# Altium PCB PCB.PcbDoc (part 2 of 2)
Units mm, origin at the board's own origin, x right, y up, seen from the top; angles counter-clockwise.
Board outline 68.58 x 53.34 mm, 4 copper layers (TOP, GND, SIG, BOTTOM), stack 1.586 mm thick; 137 components, 78 nets, 396 pads, 160 vias.
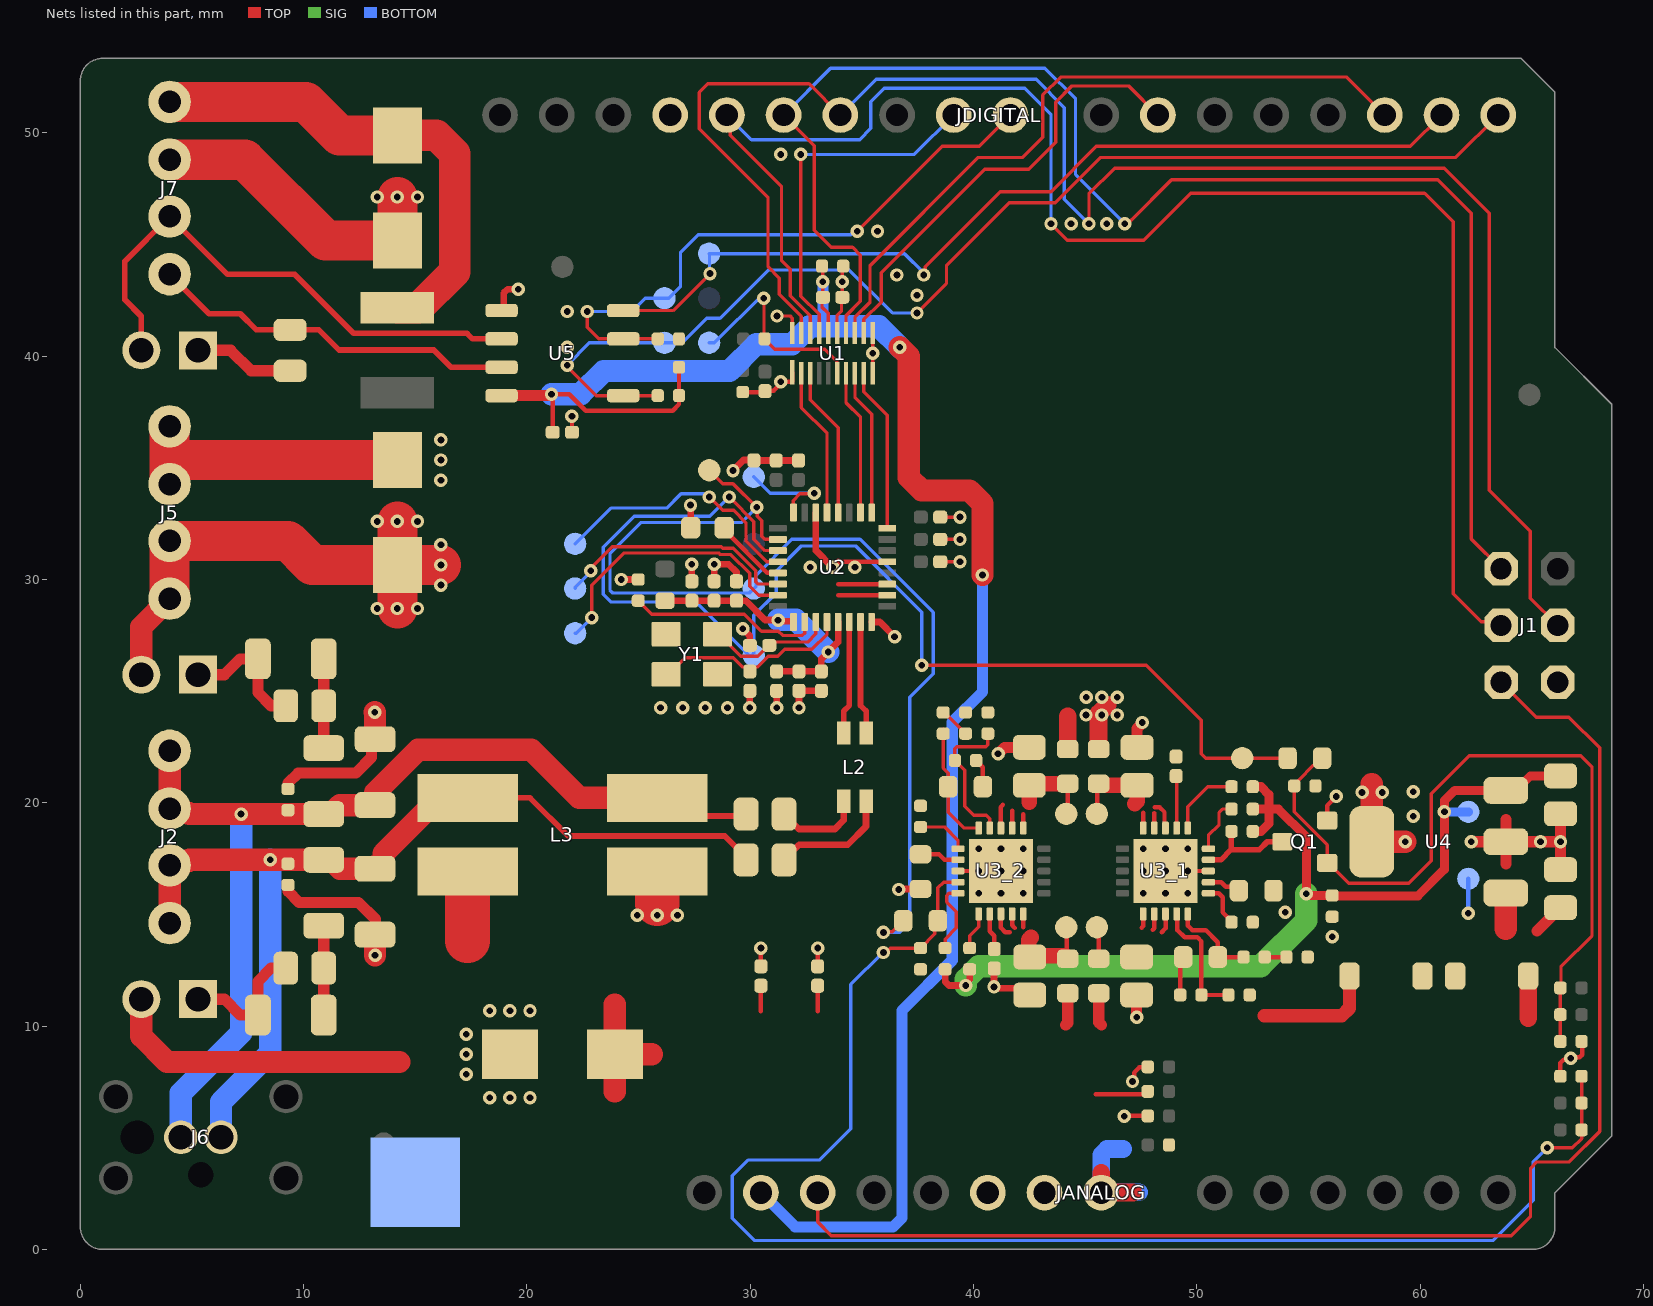
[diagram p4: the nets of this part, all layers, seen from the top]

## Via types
v1: diameter 0.6, hole 0.3, TOP to BOTTOM, tented both sides, 160 vias

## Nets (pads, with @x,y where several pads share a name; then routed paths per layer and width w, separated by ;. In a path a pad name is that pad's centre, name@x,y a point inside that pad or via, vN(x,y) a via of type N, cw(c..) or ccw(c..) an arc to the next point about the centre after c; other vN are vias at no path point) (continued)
DIGITAL8_1: DE.X JDIGITAL.9 R35.2 U5.3 | length 27.6
  TOP w0.15: v1(22.7,42) 22.7,41.3 23.225,40.775 U5.3@24.315,40.775 R35.2@25.861,40.775 ; v1(34.8,45.6) 38.6,49.4 40.256,49.4 JDIGITAL.9@41.656,50.8
  BOTTOM w0.15: v1(22.7,42) 24.706,42 25.301,42.595 26.36,42.595 26.877,43.111 26.877,44.642 27.67,45.435 34.513,45.435 34.678,45.6 v1(34.8,45.6)
DIOA0_1: DIOA0.X DIOA0_1.X R14.1 U2.18 | length 48
  TOP w0.15: DIOA0_1.X@28.165,34.895 28.765,34.295 29.23,34.295 v1(30.294,33.231) 30.317,33.208 30.317,32.831 30.517,32.631 30.517,31.938 30.66,31.795 U2.18@31.24,31.795 ; v1(35.965,14.195) 35.998,14.228 36.365,14.228 36.527,14.39 36.529,14.39 36.854,14.715 R14.1@36.854,14.717
  BOTTOM w0.15: v1(30.294,33.231) 29.618,32.555 25.12,32.555 23.718,31.153 23.718,29.529 23.852,29.395 29.96,29.395 DIOA0.X@30.16,29.595 30.26,29.695 30.26,30.195 31.865,31.8 34.919,31.8 38.196,28.524 38.196,25.774 37.141,24.719 37.141,19.133 37.151,19.122 37.151,14.651 36.695,14.195 v1(35.965,14.195)
DIOA1_1: DIOA1.X DIOA1_1.X R16.2 U2.19 | length 53.9
  TOP w0.15: v1(29.06,33.695) 29.635,33.12 29.635,33.11 30.163,32.582 30.163,31.792 30.66,31.295 U2.19@31.24,31.295 ; v1(37.684,26.16) 47.74,26.16 50.2,23.7 50.2,22.2 50.4,22 DIOA1_1.X@52.033,22 R16.2@54.067,22
  BOTTOM w0.15: v1(29.06,33.695) 28.197,32.832 24.797,32.832 23.419,31.454 23.419,29.334 23.759,28.995 27.56,28.995 29.96,26.595 30.06,26.595 30.16,26.695 30.16,27.585 30.162,27.587 30.162,28.397 31.16,29.395 31.16,30.368 32.292,31.5 34.722,31.5 37.684,28.538 v1(37.684,26.16)
GND: C1_1.2 C1_2.2 C2.1 C3.2 C4.1 C5.1 C6.1 C7.1 C8.1 C9.1 C10.1 C11.1 C12.1 C13.1 C14.1 C19.2 C20_1.1 C20_2.1 C21.1 C22.1 C23.1 C24_1.2 C24_2.2 C25.1 C26.1 C27.1 C28.1 C29.1 D3.2 D4.1 D5.2 F1.1 F3.1 J1.6 J3.2 J4.2 J5.1 J5.2 J7.3 JANALOG.6 JANALOG.7 JDIGITAL.15 L3.2 Q1.2 QR1.PAD R3.2 R4.2 R5.2 R9.2 R21.2 R22.2 R23.2 R24.1 R25.1 R26.2 R30.1 R31.1 R35.1 R36_1.1 R36_2.1 R38_1.1 R38_2.1 R39_1.1 R39_2.1 R40_1.1 R40_2.1 U1.1 U1.10 U1.11 U1.15 U1.20 U2.2 U2.3 U2.5 U2.14 U2.32 U2.33 U3_1.8 U3_1.21 U3_2.8 U3_2.21 U4.2 U4.4 U5.5 Y1.2 Y1.4 | length 131
  TOP w0.15: v1(31.2,41.8) 31.8,41.8 31.89,41.71 U1.20@31.89,41.038 ; U1.15@33.89,41.038 33.89,41.838 34.09,42.038 34.09,42.603 C4.1@34.125,42.638 v1(34.125,43.337) 34.125,43.998 R21.2@34.165,44.038 ; U1.10@35.49,39.238 v1(35.49,40.138) U1.11@35.49,41.038 ; C10.1@38.51,30.795 v1(39.395,30.795) ; C27.1@38.51,31.795 v1(39.395,31.795) ; C13.1@38.51,32.795 v1(39.395,32.795)
  TOP w0.2: v1(22.015,37.306) 22.02,37.301 22.02,36.6 C28.1@22.025,36.595 ; R22.2@29.665,38.395 30.625,38.395 30.69,38.46 31.055,38.46 31.373,38.778 v1(31.373,38.854) 31.89,38.854 U1.1@31.89,39.288 ; C29.1@30.48,12.685 v1(30.48,13.493) ; C25.1@33.02,12.685 v1(33.02,13.493) ; 33.94,29.295 U2.2@36.14,29.295 ; 33.94,29.795 U2.3@36.14,29.795 ; 33.94,30.795 U2.5@36.14,30.795 ; U3_2.8@39.304,16.945 v1(40.229,16.945) ; v1@46.763,5.975 R24.1@47.805,5.975 ; v1(47.121,7.517) 47.195,7.592 47.195,7.917 47.43,8.152 47.782,8.152 R25.1@47.805,8.175 ; v1@47.282,10.311 v1@47.305,10.334 ; v1(49.596,16.945) U3_1.8@50.521,16.945 ; Q1.2@55.84,19.206 55.84,19.875 v1(56.251,20.286) ; R30.1@66.282,7.754 66.282,8.347 66.423,8.489 66.67,8.489 v1(66.747,8.565) 66.784,8.603 67.139,8.603 67.257,8.72 67.257,9.288 R31.1@67.232,9.313
  TOP w0.3: U5.5@18.96,42.114 18.96,42.824 19.136,43 v1(19.611,43) ; v1(24.22,30) R3.2@24.985,30 ; v1(27.328,33.334) 27.332,33.33 27.332,32.323 C14.1@27.335,32.32 ; C21.1@27.385,29.92 v1(27.385,30.685) ; C7.1@28.385,29.92 v1(28.385,30.685) 29.035,30.685 29.385,30.335 C22.1@29.385,29.92 ; v1(29.231,34.878) 29.703,35.35 30.025,35.35 30.045,35.33 C11.1@31.165,35.33 C12.1@32.165,35.33 ; v1(29.66,27.795) 29.985,27.47 C5.1@29.985,27.05 ; v1(29.985,24.25) C9.1@29.985,25.015 ; v1(31.185,24.25) C6.1@31.185,25.015 ; v1(32.185,24.25) C8.1@32.185,25.015 C23.1@33.185,25.015 ; U2.14@32.94,32.995 32.94,31.295 v1(33.69,30.545) 33.94,30.795 ; U2.32@35.44,28.095 35.807,28.095 v1(36.465,27.437) ; v1(36.649,16.117) 36.674,16.142 R38_2.1@37.629,16.142 ; C20_2.1@40.919,12.572 v1(40.919,11.754) 40.977,11.697 42.216,11.697 C1_2.2@42.52,11.392
  TOP w0.5: F1.1@9.3,16.32 9.3,16.04 9.8,15.54 12.459,15.54 13.214,14.784 R4.2@13.214,14.109 ; F3.1@9.3,20.62 9.3,20.877 9.762,21.339 12.339,21.339 13.04,22.04 13.04,22.685 R5.2@13.2,22.845 ; v1(41.101,22.195) 41.387,22.481 C24_2.2@42.499,22.482 ; v1(47.305,10.392) C24_1.2@47.305,11.392 ; C1_1.2@47.326,22.482 47.326,23.334 47.56,23.568 v1(47.56,23.595) ; v1(62.29,18.256) U4.2@63.84,18.256 ; 63.84,17.256 U4.2@63.84,18.256 ; 63.84,19.256 U4.2@63.84,18.256 ; C3.2@66.29,17.006 v1(66.29,18.256) ; C19.2@66.29,19.506 v1(66.29,18.256) ; U4.2@63.84,18.256 v1(65.39,18.256) v1(66.29,18.256)
  TOP w1: J3.2@2.73,11.205 2.73,9.551 3.888,8.392 14.284,8.392 ; J4.2@2.73,25.735 2.73,27.87 J5.1@4,29.14 ; v1(13.185,24.05) 13.2,24.035 R5.2@13.2,22.845 ; v1(13.2,13.17) R4.2@13.2,14.095 ; 57.84,20.84 U4.4@57.84,18.256 v1(59.34,18.256)
  TOP w1.8: J5.1@4,29.14 J5.2@4,31.73 9.305,31.73 10.385,30.65 D5.2@14.2,30.65 ; J7.3@4,48.8 7.365,48.8 10.985,45.18 D4.1@14.2,45.18 v1(14.2,47.13) ; v1(14.2,28.7) D5.2@14.2,30.65 ; v1(14.2,32.6) D5.2@14.2,30.65 ; v1(16.15,30.65) D5.2@14.2,30.65
  TOP w2: 25.84,15.487 L3.2@25.84,16.92
  other v1: 46.749,5.961 18.34,6.787 19.24,6.787 20.14,6.787 17.29,7.837 17.29,8.737 17.29,9.637 18.34,10.687 19.24,10.687 20.14,10.687 56.06,14.003 24.94,14.97 25.84,14.97 26.74,14.97 53.96,15.095 40.229,15.945 41.229,15.945 42.229,15.945 47.596,15.945 48.596,15.945 49.596,15.945 41.229,16.945 42.229,16.945 47.596,16.945 48.596,16.945 40.229,17.945 41.229,17.945 42.229,17.945 47.596,17.945 48.596,17.945 49.596,17.945 59.7,19.4 57.402,20.464 58.302,20.464 59.7,20.5 25.985,24.25 26.985,24.25 27.985,24.25 28.985,24.25 13.3,28.7 15.1,28.7 16.15,29.75 32.69,30.545 34.69,30.545 16.15,31.55 13.3,32.6 15.1,32.6 21.8,40.4 21.8,42 37.47,42.735 36.57,43.635 35.7,45.6 44.37,45.935 45.97,45.935 13.3,47.13 15.1,47.13 31.37,49.035
I\R\Q\_\N\_2: U1.8 U2.9 | length 6.6
  TOP w0.15: U1.8@34.69,39.238 34.69,38.156 35.44,37.406 U2.9@35.44,32.995
IOREF: C4.2 C28.2 JANALOG.2 R21.1 R32.2 R33.2 U1.16 U5.8 | length 84.7
  TOP w0.15: R21.1@33.215,44.038 33.255,43.998 v1(33.255,43.337) C4.2@33.255,42.638 33.215,42.598 33.215,42.194 33.49,41.919 U1.16@33.49,41.038
  TOP w0.2: C28.2@21.155,36.595 21.155,38.245 v1(21.1,38.3) 21.9,38.3 22.641,37.559 26.525,37.559 26.811,37.845 R32.2@26.811,38.235 R33.2@26.811,39.505
  TOP w0.5: U5.8@18.865,38.235 21.008,38.235 21.073,38.3 v1(21.1,38.3)
  TOP w1: v1(36.7,40.4) 37.1,40 37.1,34.568 37.686,33.982 39.814,33.982 40.4,33.397 v1(40.4,30.2)
  BOTTOM w0.5: JANALOG.2@30.48,2.54 32.02,1 36.4,1 36.8,1.4 36.8,10.7 39.048,12.948 39.048,23.618 40.4,24.97 v1(40.4,30.2) ; v1(33.255,43.337) 33.255,41.65 33.57,41.335
  BOTTOM w1: v1(21.1,38.3) 22.409,38.3 23.444,39.335 29.07,39.335 30.27,40.535 31.87,40.535 32.67,41.335 33.57,41.335 35.765,41.335 v1(36.7,40.4)
LDO_OUT: C19.1 LDO_OUT.X R8.1 R10_1.2 R10_2.2 R11_1.2 R11_2.2 R26.1 U4.3 | length 45.2
  TOP w0.3: R10_2.2@38.729,12.542 38.729,11.993 38.905,11.817 v1(39.654,11.817) 39.654,11.898 39.829,12.073 R11_2.2@39.829,12.542
  TOP w0.4: R8.1@52.508,18.72 52.879,18.72 53.229,19.071 53.229,19.72 ; R10_1.2@52.508,19.72 53.229,19.72 ; R11_1.2@52.508,20.72 52.879,20.72 53.229,20.37 53.229,19.72 ; C19.1@66.29,21.206 64.944,21.206 64.294,20.556 61.552,20.556 61.089,20.093 61.089,17.015 59.905,15.832 56.081,15.832 R26.1@56.064,15.849 54.988,15.849 v1(54.905,15.932) 54.905,18.469 53.654,19.72 53.229,19.72
  SIG w1: v1(39.654,11.817) 39.654,12.095 40.24,12.681 52.857,12.681 54.905,14.729 v1(54.905,15.932)
  BOTTOM w0.4: v1(61.09,19.595) LDO_OUT.X@62.16,19.595
MISO_1: J1.1 JDIGITAL.13 U1.14 | length 66.5
  TOP w0.15: JDIGITAL.13@31.496,50.8 32.865,49.431 32.865,45.643 33.635,44.873 34.582,44.873 34.925,44.53 34.925,42.454 34.29,41.82 U1.14@34.29,41.038 ; v1(46.77,45.935) 46.892,45.935 47.047,46.09 47.057,46.09 48.867,47.9 60.8,47.9 62.294,46.406 62.294,31.813 J1.1@63.627,30.48
  BOTTOM w0.15: JDIGITAL.13@31.496,50.8 33.596,52.9 43.2,52.9 44.57,51.53 44.57,48.135 v1(46.77,45.935)
MOSI_1: J1.4 JDIGITAL.12 U1.19 | length 76.9
  TOP w0.15: U1.19@32.29,41.038 32.29,41.781 31.3,42.771 31.3,43.5 30.8,44 30.8,47.088 27.712,50.176 27.712,51.812 28.1,52.2 32.636,52.2 JDIGITAL.12@34.036,50.8 ; v1(45.17,45.935) 45.17,47.27 46.318,48.418 61.082,48.418 63.1,46.4 63.1,34 64.94,32.16 64.94,29.167 J1.4@66.167,27.94
  BOTTOM w0.15: JDIGITAL.12@34.036,50.8 35.636,52.4 42.805,52.4 44.07,51.135 44.07,47.035 v1(45.17,45.935)
NetC1_1_1: C1_1.1 OUT_1.X R2_1.2 U3_1.13 U3_1.14 U3_1.15 | length 6.5
  TOP w0.2: OUT_1.X@45.546,19.526 R2_1.2@45.546,20.857 ; U3_1.15@47.596,18.87 47.596,19.554 ; U3_1.14@48.096,18.87 48.096,19.542 ; 48.126,19.805 48.332,19.805 48.553,19.584 U3_1.13@48.553,18.87
  TOP w0.7: R2_1.2@45.605,20.857 45.665,20.797 45.943,20.797 R2_1.2@45.962,20.778 ; R2_1.2@45.968,20.778 C1_1.1@47.322,20.778 ; 47.226,19.963 47.326,20.063 C1_1.1@47.326,20.782
NetC1_2_1: C1_2.1 OUT_2.X R2_2.2 U3_2.13 U3_2.14 U3_2.15 | length 6.3
  TOP w0.2: U3_2.13@41.229,15.02 41.229,14.402 41.426,14.205 41.626,14.205 ; U3_2.14@41.729,15.02 41.729,14.517 41.852,14.393 ; 42.229,14.426 U3_2.15@42.229,15.02 ; R2_2.2@44.176,13.074 OUT_2.X@44.176,14.389
  TOP w0.7: 42.577,13.968 42.477,13.868 42.477,13.149 44.101,13.149 R2_2.2@44.176,13.074
NetC3_1: "POWER OR.X" C3.1 D1.C D2.C U4.1 | length 4.6
  TOP w0.5: 65.24,14.256 C3.1@66.29,15.306
  TOP w1: 63.84,14.356 U4.1@63.84,15.956
  BOTTOM w0.2: v1(62.16,15.056) 62.16,16.595
NetC5_2: C5.2 U2.27 Y1.3 | length 5.8
  TOP w0.15: Y1.3@28.535,27.55 28.58,27.55 29.351,26.779 29.572,26.558 30.338,26.558 30.83,27.05 30.878,27.05 31.027,27.199 32.575,27.199 32.94,27.565 U2.27@32.94,28.095
NetC6_2: C6.2 C7.2 C8.2 C21.2 C22.2 C23.2 L1.2 U2.25 U2.29 | length 13.5
  TOP w0.3: L1.2@26.185,29.05 C21.2@27.385,29.05 C7.2@28.385,29.05 29.808,29.05 30.671,28.187 31.24,28.187 v1(31.247,28.18) 31.304,28.124 31.94,28.124 U2.25@31.94,28.095 ; C6.2@31.185,25.885 C23.2@33.185,25.885 33.185,26.447 v1(33.492,26.754) 33.94,27.202 U2.29@33.94,28.095
  BOTTOM w1: v1@31.26,28.195 32.052,28.195 v1(33.492,26.754)
NetC9_2: C9.2 U2.28 Y1.1 | length 9
  TOP w0.15: Y1.1@26.235,25.75 26.335,25.75 27.087,26.502 29.237,26.502 29.66,26.078 29.792,26.078 C9.2@29.985,25.885 30.178,26.078 30.315,26.078 30.518,26.281 30.52,26.281 30.797,26.558 31.231,26.558 31.542,26.869 32.755,26.869 33.44,27.554 U2.28@33.44,28.095
NetC14_2: C14.2 U2.21 | length 3.1
  TOP w0.2: C14.2@28.943,32.12 30.768,30.295 U2.21@31.24,30.295
NetC15_1: C15.1 L2.2 | length 4
  TOP w0.3: C15.1@31.515,19.495 31.515,19.369 31.912,18.971 32.038,18.971 32.181,18.829 33.797,18.829 34.19,19.222 L2.2@34.19,20.075
NetC15_2: C15.2 F3.2 J2.3 J2.4 J6.1 L3.1 R5.1 R7.1 | length 46.8
  TOP w0.254: L3.1@25.84,20.22 26.653,19.407 29.727,19.407 C15.2@29.815,19.495
  TOP w1: J2.4@4,22.33 J2.3@4,19.74 4.172,19.568 4.809,19.568 4.881,19.495 11.23,19.495 11.63,19.895 R5.1@13.1,19.895 ; R5.1@13.2,19.895 13.2,20.444 15.126,22.37 20.196,22.37 22.346,20.22 L3.1@25.84,20.22
  BOTTOM w1: J6.1@4.5,5.02 4.5,7 7.2,9.7 v1@7.2,19.5
  other v1: 7.2,19.495
NetC16_1: C16.1 L2.3 | length 5.5
  TOP w0.3: C16.1@31.515,17.445 31.515,17.571 31.912,17.968 32.038,17.968 32.192,18.122 34.368,18.122 35.19,18.944 L2.3@35.19,20.075
NetC16_2: C16.2 F1.2 J2.1 J2.2 J6.2 L3.4 R4.1 R6.1 | length 44.6
  TOP w0.254: L3.4@17.34,20.22 20.14,20.22 21.85,18.51 28.863,18.51 29.815,17.558 C16.2@29.815,17.445
  TOP w1: J2.1@4,14.61 J2.2@4,17.2 4.172,17.372 4.809,17.372 4.881,17.445 R6.1@10.9,17.445 ; R6.1@11.23,17.445 11.63,17.045 R4.1@13.1,17.045 ; R4.1@13.2,17.155 R4.1@13.2,17.045 13.497,17.045 13.577,17.125 13.577,17.725 15.497,19.645 16.765,19.645 L3.4@17.34,20.22
  BOTTOM w1: J6.2@6.3,5.02 6.3,6.6 8.5,8.8 v1(8.5,17.445)
NetC17_1: C17.1 R6.2 R27.1 | length 4
  TOP w0.5: R27.1@10.9,10.495 C17.1@10.9,12.595 R6.2@10.9,14.495
NetC17_2: C17.2 J3.1 R27.2 | length 5.6
  TOP w0.5: J3.1@5.27,11.205 6.451,11.205 7.161,10.495 R27.2@7.95,10.495 ; R27.2@7.95,10.825 7.95,12 8.545,12.595 C17.2@9.2,12.595
NetC18_1: C18.1 R7.2 R41.1 | length 4
  TOP w0.5: R7.2@10.9,22.445 C18.1@10.9,24.345 R41.1@10.9,26.445
NetC18_2: C18.2 J4.1 R41.2 | length 5.6
  TOP w0.5: J4.1@5.27,25.735 6.451,25.735 7.161,26.445 R41.2@7.95,26.445 ; R41.2@7.95,26.115 7.95,24.94 8.545,24.345 C18.2@9.2,24.345
NetC20_1_2: C20_1.2 U3_1.12 | length 2.3
  TOP w0.15: C20_1.2@49.077,21.197 49.096,21.177 U3_1.12@49.096,18.87
NetC20_2_2: C20_2.2 U3_2.12 | length 1.7
  TOP w0.2: U3_2.12@40.729,15.02 40.729,14.249 40.929,14.049 C20_2.2@40.929,13.452
NetC24_1_1: C24_1.1 IN_1.X R12_1.2 R13_1.2 R15_1.1 U3_1.1 U3_1.2 U3_1.3 | length 5.3
  TOP w0.2: R15_1.1@45.599,13.024 IN_1.X@45.599,14.271 ; 47.526,14.405 47.602,14.482 U3_1.1@47.602,15.015 ; 48.026,14.305 48.102,14.382 U3_1.2@48.102,15.015 ; 48.426,14.205 48.602,14.382 U3_1.3@48.602,15.015 ; R12_1.2@49.258,11.392 49.258,12.957 R13_1.2@49.393,13.092
  TOP w0.7: R15_1.1@45.605,13.017 R15_1.1@45.617,13.005
NetC24_2_1: C24_2.1 IN_2.X R12_2.2 R13_2.2 R15_2.1 U3_2.1 U3_2.2 U3_2.3 | length 7.8
  TOP w0.2: R12_2.2@40.117,21.897 40.117,21.889 40.417,21.59 R13_2.2@40.417,20.782 ; 41.223,19.809 41.32,19.905 ; U3_2.3@41.229,18.87 41.229,19.645 41.229,19.809 ; U3_2.2@41.729,18.87 41.729,19.645 ; U3_2.1@42.229,18.87 42.229,19.494 ; IN_2.X@44.22,19.541 R15_2.1@44.22,20.857
  TOP w0.7: 42.499,20.022 C24_2.1@42.499,20.782 ; C24_2.1@42.72,20.576 42.514,20.782 42.589,20.857 R15_2.1@44.214,20.857
NetD4_2: D4.2 F2.2 J7.4 | length 22.3
  TOP w1.4: F2.2@14.2,42.165 15.15,42.165 16.77,43.785 16.77,49.08 15.95,49.9 14.22,49.9 D4.2@14.2,49.88
  TOP w1.8: J7.4@4,51.39 10.1,51.39 11.61,49.88 D4.2@14.2,49.88
NetDIO_B0_X: DIO_B0.X U2.16 | length 4.6
  TOP w0.15: U2.16@31.94,32.995 31.92,33.015 31.92,33.532 32.225,33.837 32.844,33.837 v1(32.868,33.861)
  BOTTOM w0.15: DIO_B0.X@30.16,34.595 30.894,33.861 v1(32.868,33.861)
NetDIOA2_X: DIOA2.X U2.20 | length 11.7
  TOP w0.15: v1(28.16,33.695) 28.76,33.095 29.258,33.095 29.809,32.544 29.809,31.725 30.74,30.795 U2.20@31.24,30.795
  BOTTOM w0.15: DIOA2.X@22.16,31.595 23.765,33.2 26.265,33.2 26.901,33.836 27.898,33.836 28.038,33.695 v1(28.16,33.695)
NetDIOA3_X: DIOA3.X U2.22 | length 10.9
  TOP w0.15: v1(22.86,30.395) 22.86,30.495 23.829,31.464 28.708,31.464 28.776,31.395 29.241,31.395 30.249,30.387 30.249,29.905 30.36,29.795 U2.22@31.24,29.795
  BOTTOM w0.15: DIOA3.X@22.16,29.595 22.16,29.645 22.86,30.345 v1(22.86,30.395)
NetDIOA4_X: DIOA4.X U2.23 | length 12.5
  TOP w0.15: v1(22.91,28.295) 22.91,29.735 24.362,31.187 28.593,31.187 28.662,31.118 29.126,31.118 29.972,30.272 29.972,29.698 30.376,29.295 U2.23@31.24,29.295
  BOTTOM w0.15: DIOA4.X@22.16,27.595 22.21,27.595 v1(22.91,28.295)
NetJ7_1: J7.1 R34.2 U5.7 | length 16.6
  TOP w0.254: J7.1@4,43.67 5.77,41.9 7.165,41.9 7.885,41.18 R34.2@9.395,41.18 10.685,41.18 11.591,40.274 15.831,40.274 16.6,39.505 U5.7@18.865,39.505
NetJ7_2: J7.2 J12.2 U5.6 | length 24.3
  TOP w0.254: J12.2@2.73,40.265 2.73,41.79 1.995,42.525 1.995,44.255 J7.2@4,46.26 6.595,43.665 9.6,43.665 12.242,41.023 17.314,41.023 17.562,40.775 U5.6@18.865,40.775
NetJ12_1: J12.1 R34.1 | length 4.5
  TOP w0.5: J12.1@5.27,40.265 6.735,40.265 7.65,39.35 R34.1@9.395,39.35
NetJDIGITAL_3: JDIGITAL.3 U1.13 | length 31.7
  TOP w0.15: U1.13@34.69,41.038 34.69,41.735 35.365,42.41 35.365,44.045 40.22,48.9 42.2,48.9 43.1,49.8 43.1,51.7 43.9,52.5 56.72,52.5 JDIGITAL.3@58.42,50.8
NetJDIGITAL_7: JDIGITAL.7 U1.12 | length 20.5
  TOP w0.15: U1.12@35.09,41.038 35.09,41.644 35.865,42.419 35.865,43.737 40.499,48.371 42.471,48.371 43.677,49.577 43.677,51.375 44.402,52.1 46.96,52.1 JDIGITAL.7@48.26,50.8
NetJDIGITAL_10: JDIGITAL.10 U1.17 | length 15.9
  TOP w0.15: v1(32.27,49.035) 32.27,42.692 33.09,41.872 U1.17@33.09,41.038
  BOTTOM w0.15: v1(32.27,49.035) 37.351,49.035 JDIGITAL.10@39.116,50.8
NetL2_1: L2.1 U2.30 | length 5.1
  TOP w0.254: L2.1@34.19,23.125 34.19,24.11 34.44,24.36 U2.30@34.44,28.095
NetL2_4: L2.4 U2.31 | length 5.1
  TOP w0.254: U2.31@34.94,28.095 34.94,24.36 35.19,24.11 L2.4@35.19,23.125
NetQ1_1: Q1.1 R9.1 R16.1 R28.1 R29.1 R31.2 | length 34.9
  TOP w0.15: R16.1@55.617,22 55.617,21.998 55.292,21.673 55.221,21.673 54.565,21.016 54.565,21.006 54.365,20.806 R9.1@54.365,20.756 54.36,20.751 54.36,19.592 55.84,18.112 Q1.1@55.84,17.306 55.894,17.306 56.8,16.4 59.5,16.4 60.5,17.4 60.5,20.4 62.2,22.1 67.2,22.1 67.7,21.6 67.7,14.056 66.308,12.665 66.308,11.74 R29.1@66.282,11.713 ; R31.2@66.282,9.313 R28.1@66.282,10.313 ; R28.1@66.282,10.513 66.282,11.513 R29.1@66.308,11.54
NetQ1_3: Q1.3 R8.2 U3_1.9 | length 4.7
  TOP w0.25: U3_1.9@50.521,17.445 51.084,17.445 51.538,17.9 ; R8.2@51.558,18.72 51.538,18.701 51.538,17.9 ; Q1.3@53.716,18.132 Q1.3@53.84,18.256 53.156,18.256 52.8,17.9 51.538,17.9
NetR1_2: R1.2 TRANSLATOR_OE.X U1.6 | length 9.3
  TOP w0.15: v1(30.6,42.6) 30.62,42.58 30.62,40.795 31.098,40.317 33.334,40.317 33.792,39.859 33.802,39.859 33.89,39.771 U1.6@33.89,39.238
  BOTTOM w0.15: TRANSLATOR_OE.X@28.16,40.605 28.39,40.605 28.63,40.845 28.645,40.845 30.314,42.514 30.514,42.514 v1(30.6,42.6)
NetR3_1: R3.1 U2.26 | length 8.6
  TOP w0.15: R3.1@24.985,29.05 25.592,28.442 29.737,28.442 30.503,27.676 31.263,27.676 31.447,27.493 32.152,27.493 ; 32.152,27.493 32.338,27.493 32.44,27.595 U2.26@32.44,28.095
NetR10_1_1: R10_1.1 U3_1.10 | length 2.5
  TOP w0.15: U3_1.10@50.521,17.945 50.521,18.548 50.996,19.023 50.996,19.568 51.149,19.72 R10_1.1@51.652,19.72
NetR10_2_1: R10_2.1 U3_2.10 | length 3.3
  TOP w0.15: R10_2.1@38.729,13.492 38.729,13.897 39.229,14.397 39.229,15.128 38.803,15.554 38.803,15.847 38.901,15.945 U3_2.10@39.304,15.945
NetR11_1_1: R11_1.1 U3_1.11 | length 3.3
  TOP w0.15: U3_1.11@49.596,18.87 49.596,19.831 50.486,20.72 R11_1.1@51.558,20.72
NetR11_2_1: R11_2.1 U3_2.11 | length 1.7
  TOP w0.15: R11_2.1@39.829,13.492 39.829,14.053 40.229,14.453 U3_2.11@40.229,15.02
NetR12_1_1: R12_1.1 R36_1.2 U3_1.4 | length 5.6
  TOP w0.2: U3_1.4@49.096,15.02 49.129,14.988 49.129,14.3 49.456,13.973 50.027,13.973 50.208,13.792 R12_1.1@50.208,11.392 R36_1.2@51.419,11.392
NetR12_2_1: R12_2.1 R36_2.2 U3_2.4 | length 6.6
  TOP w0.15: R36_2.2@40.639,23.093 40.639,22.594 40.551,22.506 39.255,22.506 39.167,22.418 R12_2.1@39.167,21.897 39.602,21.462 39.602,19.853 40.016,19.439 40.575,19.439 40.729,19.285 U3_2.4@40.729,18.87
NetR13_1_1: R13_1.1 R37_1.2 U3_1.5 | length 4
  TOP w0.2: U3_1.5@49.596,15.02 49.596,14.504 49.8,14.3 50.4,14.3 50.943,13.757 R13_1.1@50.943,13.092 R37_1.2@52.093,13.092
NetR13_2_1: R13_2.1 R37_2.2 U3_2.5 | length 5.5
  TOP w0.15: R37_2.2@38.642,23.297 38.642,21.557 38.867,21.332 R13_2.1@38.867,20.72 38.867,19.578 39.575,18.87 U3_2.5@40.229,18.87
NetR14_2: R14.2 R19.1 R20.1 R23.1 R30.2 U3_2.9 | length 66.1
  TOP w0.15: v1(35.965,13.295) 36.081,13.295 36.278,13.492 R23.1@37.629,13.492 38.269,14.132 38.269,14.582 R14.2@38.404,14.717 38.404,16.192 38.658,16.445 U3_2.9@39.304,16.445 ; v1(65.69,4.556) 66.823,4.556 67.232,4.964 R20.1@67.232,5.354 ; R20.1@67.232,5.554 R19.1@67.232,6.554 ; R19.1@67.232,6.754 R30.2@67.232,7.754
  BOTTOM w0.15: v1(35.965,13.295) 35.932,13.295 34.5,11.863 34.5,5.4 33.1,4 29.9,4 29.2,3.3 29.2,1.4 30.205,0.395 63.26,0.395 65.06,2.195 65.06,3.926 v1(65.69,4.556)
NetR37_1_1: R37_1.1 R39_1.2 | length 1
  TOP w0.2: R37_1.1@53.043,13.092 54.007,13.092 R39_1.2@54.016,13.101
NetR37_2_1: R37_2.1 R39_2.2 | length 1.4
  TOP w0.15: R37_2.1@38.642,24.047 38.692,24.047 R39_2.2@39.642,23.097
NetR38_1_2: R38_1.2 U3_1.7 | length 1.4
  TOP w0.2: U3_1.7@50.521,16.445 51.092,16.445 51.299,16.238 51.612,16.238 R38_1.2@51.784,16.066
NetR38_2_2: R38_2.2 U3_2.7 | length 1.8
  TOP w0.2: R38_2.2@37.629,17.692 38.454,17.692 38.701,17.445 U3_2.7@39.304,17.445
NetR40_1_2: R40_1.2 U3_1.6 | length 2
  TOP w0.2: U3_1.6@50.521,15.945 50.98,15.945 51.159,15.766 51.159,15.089 51.382,14.865 R40_1.2@51.594,14.653
NetR40_2_2: R40_2.2 U3_2.6 | length 2.3
  TOP w0.15: R40_2.2@37.629,18.915 38.721,18.915 39.304,18.332 U3_2.6@39.304,17.945
R\E\S\E\T\_1: J1.5 JANALOG.3 | length 62.6
  TOP w0.15: JANALOG.3@33.02,2.54 33.02,1.226 33.635,0.611 64.077,0.611 64.947,1.481 64.947,3.641 65.22,3.914 66.672,3.914 68.038,5.279 68.038,22.462 66.666,23.834 65.193,23.834 J1.5@63.627,25.4
R\E\S\E\T\_\N\_2: U1.9 U2.8 | length 7.4
  TOP w0.15: U1.9@35.09,39.238 35.09,38.41 36.14,37.36 U2.8@36.14,32.295
SCLK_1: J1.3 JDIGITAL.14 U1.18 | length 72.4
  TOP w0.15: JDIGITAL.14@28.956,50.8 29.105,50.651 29.105,49.9 31.4,47.605 31.4,44.3 31.8,43.9 31.8,42.701 32.69,41.811 U1.18@32.69,41.038 ; v1(43.47,45.935) 44.205,45.2 47.635,45.2 49.735,47.3 60.2,47.3 61.484,46.016 61.484,29.362 62.74,28.106 63.461,28.106 J1.3@63.627,27.94
  BOTTOM w0.15: JDIGITAL.14@28.956,50.8 30.056,49.7 34.9,49.7 35.4,50.2 35.4,51.4 36,52 42.3,52 43.47,50.83 v1(43.47,45.935)
SCLK_2: U1.3 U2.12 | length 6.8
  TOP w0.15: U1.3@32.69,39.238 32.69,38.055 33.94,36.805 U2.12@33.94,32.995
SDI_2: U1.2 U2.13 | length 6.7
  TOP w0.15: U1.2@32.29,39.238 32.29,37.702 33.44,36.552 U2.13@33.44,32.995
SDO_2: U1.7 U2.10 | length 6.5
  TOP w0.15: U1.7@34.29,39.238 34.29,37.924 34.94,37.274 U2.10@34.94,32.995
T1S_POWER: C25.2 C29.2 D2.A D3.1 L3.3 R2_2.1 R15_1.2 R18.2 | length 21.7
  TOP w0.2: 30.48,10.666 C29.2@30.48,11.807 ; 33.02,10.666 C25.2@33.02,11.807 ; 45.484,6.956 47.686,6.956 R18.2@47.805,7.075
  TOP w0.5: 44.129,10.045 44.22,10.137 R2_2.1@44.22,11.467 ; R15_1.2@45.605,11.467 45.605,10.169 45.729,10.045
  TOP w0.6: 53.016,10.456 56.489,10.456 56.84,10.807 D2.A@56.84,12.305
  TOP w1: 23.94,7.07 D3.1@23.94,8.737 ; 23.94,10.968 D3.1@23.94,8.737 ; 25.584,8.737 D3.1@23.94,8.737
  TOP w2: 17.34,13.82 L3.3@17.34,16.92
UART.RX_1: JDIGITAL.1 R32.1 RO.X U5.1 | length 53.1
  TOP w0.15: v1(21.8,39.6) 21.8,39.536 23.101,38.235 U5.1@24.315,38.235 R32.1@25.861,38.235 ; v1(37.47,41.935) 38.79,43.255 38.79,44.055 41.606,46.871 43.671,46.871 45.7,48.9 61.6,48.9 JDIGITAL.1@63.5,50.8
  BOTTOM w0.15: v1(21.8,39.6) 22.795,40.595 RO.X@26.16,40.595 26.96,40.595 28.06,41.695 28.65,41.695 30.815,43.86 34.445,43.86 36.37,41.935 v1(37.47,41.935)
UART.TX_1: DI.X JDIGITAL.2 U5.4 | length 41.8
  TOP w0.15: U5.4@24.315,42.045 26.545,42.045 v1(28.2,43.7) ; v1(37.77,43.635) 37.838,43.703 37.838,44.01 41.199,47.371 43.471,47.371 45.5,49.4 59.56,49.4 JDIGITAL.2@60.96,50.8
  BOTTOM w0.15: DI.X@28.16,44.595 28.18,44.575 28.18,43.72 v1(28.2,43.7) ; DI.X@28.2,44.595 36.91,44.595 37.77,43.735 v1(37.77,43.635)
VIN: D1.A D5.1 J5.3 J5.4 JANALOG.8 R2_1.1 R15_2.2 R17.2 | length 25
  TOP w0.8: R15_2.2@44.22,22.407 44.22,23.856 ; R2_1.1@45.605,22.407 45.605,24.002 45.996,24.392 ; 45.72,3.42 JANALOG.8@45.72,2.54 47.14,2.54 ; 64.842,10.358 D1.A@64.842,12.242
  TOP w1.8: J5.3@4,34.27 4,35.35 ; J5.4@4,36.86 4,35.35 ; D5.1@14.2,35.35 4,35.35
  BOTTOM w0.8: JANALOG.8@45.72,2.54 JANALOG.8@45.72,2.557 ; 46.7,4.5 45.985,4.5 45.72,4.235 JANALOG.8@45.72,2.557 ; 47.415,2.557 JANALOG.8@45.72,2.557
  other v1: 45.04,23.931 45.74,23.931 46.44,23.931 45.051,24.731 45.751,24.731 46.44,24.731 16.15,34.45 16.15,35.35 16.15,36.25
pads on no net: Fiducial_1.1 Fiducial_2.1 Fiducial_3.1 J1.2 J6.FIX J6.SHIELD JANALOG.1 JANALOG.13 JANALOG.14 JDIGITAL.4 JDIGITAL.5 JDIGITAL.6 JDIGITAL.11 JDIGITAL.16 JDIGITAL.17 JDIGITAL.18 U2.1 U2.6 U2.15 U2.24 U3_1.16 U3_1.17 U3_1.18 U3_1.19 U3_1.20 U3_2.16 U3_2.17 U3_2.18 U3_2.19 U3_2.20

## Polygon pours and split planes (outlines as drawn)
VIN on TOP "VIN_L01_P067" (solid, remove dead copper, pour order 67): 44.9,1.4 44.9,8.1 53.9,8.1 56.074,10 62.3,10 64.2,11.9 65.5,11.9 65.6,11.8 65.6,1.4
GND on TOP "GND_L01_P073" (solid, remove dead copper, pour order 73): 0,1 0,52.34 cw(c1,52.34) 1,53.34 64.516,53.34 66.04,51.816 66.04,40.386 68.58,37.846 68.58,5.08 66.04,2.54 66.04,1 cw(c65.04,1) 65.04,0 1,0 cw(c1,1)
+5V on TOP "+5V_L01_P024" (solid, remove dead copper, pour order 24): 42.96,30.195 42.96,43.795 42.06,44.695 39.86,44.695 36.56,41.395 36.56,30.195
T1S_POWER on TOP "NONET_L04_P-001" (solid, remove dead copper, pour order 72): 27.427,13.97 19.99,13.97 18.359,15.601 16.327,15.601 16.327,11.445 22.251,11.445 22.251,6.234 47.197,6.234 49,8.037 54.337,8.037 54.7,8.4 54.7,10.795 54.077,11.445 29.952,11.445
+3V3 on TOP "+3V3_L01_P058" (solid, remove dead copper, pour order 58): 39.5,26.9 39.5,29 38.075,30.425 38.075,32.735 36.7,32.735 36.7,26.9 37.8,26.9
NetC3_1 on TOP "NETC3_1_L01_P069" (solid, remove dead copper, pour order 69): 58.6,13.8 58.6,10.6 61.6,10.6 64.3,13.3 65.7,13.3 66.2,13.8 66.2,15.2 66.186,15.2 65.886,15.5 60.3,15.5
NetC24_1_1 on TOP "NETC24_1_1_L01_P062" (solid, remove dead copper, pour order 62): 49.423,13.945 48.383,14.985 45.2,14.985 45,14.785 45,12.793 45.422,12.37 49.808,12.363 49.933,12.453 49.933,13.833 49.821,13.945
NetC24_2_1 on TOP "NETC24_2_1_L01_P064" (solid, remove dead copper, pour order 64): 40.403,19.945 41.443,18.905 44.626,18.905 44.826,19.105 44.826,21.098 44.403,21.52 40.018,21.528 39.892,21.438 39.892,20.057 40.004,19.945
VIN on TOP "NONET_L04_P-001" (solid, remove dead copper, pour order 70): 43.76,25.442 43.76,23.291 46.76,23.291 46.76,25.442
NetC1_2_1 on TOP "NETC1_2_1_L01_P078" (solid, remove dead copper, pour order 78): 44.856,12.825 44.756,12.725 41.856,12.725 41.456,13.125 41.456,14.325 42.156,15.025 44.756,15.025 44.856,14.925
NetC1_1_1 on TOP "NETC1_1_1_L01_P076" (solid, remove dead copper, pour order 76): 44.926,21.105 45.026,21.205 47.926,21.205 48.326,20.805 48.326,19.605 47.626,18.905 45.026,18.905 44.926,19.005
+5V on BOTTOM "+5V_L04_P074" (solid, remove dead copper, pour order 74): 40.95,27.504 36.926,23.157 36.926,0 45.16,0 45.16,22.066 44.07,23.157 44.07,25.447 44.07,30.73 42.605,32.195 40.95,32.195
VIN on BOTTOM "VIN_L04_P075" (solid, remove dead copper, pour order 75): 15.16,32.495 15.16,39.695 55.06,39.695 59.16,35.595 59.16,7.595 53.611,2.045 44.661,2.045 44.661,30.939 41.305,34.295 28.26,34.295 26.46,32.495 15.26,32.495
GND on BOTTOM "GND_L04_P077" (solid, remove dead copper, pour order 77): 0,1 0,52.34 cw(c1,52.34) 1,53.34 64.516,53.34 66.04,51.816 66.04,40.386 68.58,37.846 68.58,5.08 66.04,2.54 66.04,1 cw(c65.04,1) 65.04,0 1,0 cw(c1,1)
+5V on BOTTOM "+5V_L04_P052" (solid, remove dead copper, pour order 52): 41.56,47.995 40.76,48.795 21.74,48.795 17.6,44.6 12.4,44.6 12.4,40.595 12.4,39.1 14.7,39.1 14.7,40.595 41.56,40.595
GND on GND "GND_L02_P079" (solid, remove dead copper, pour order 79): 0,1 0,52.34 cw(c1,52.34) 1,53.34 64.516,53.34 66.04,51.816 66.04,40.386 68.58,37.846 68.58,5.08 66.04,2.54 66.04,1 cw(c65.04,1) 65.04,0 1,0 cw(c1,1)
GND on SIG "GND_L03_P071" (solid, remove dead copper, pour order 71): 0,1 0,52.34 cw(c1,52.34) 1,53.34 64.516,53.34 66.04,51.816 66.04,40.386 68.58,37.846 68.58,5.08 66.04,2.54 66.04,1 cw(c65.04,1) 65.04,0 1,0 cw(c1,1)

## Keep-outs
TOP:
  region: 12.1,0 12.1,15.97 35.965,15.97 35.965,28.043 33.864,28.043 33.864,25.336 33.864,24.519 32.754,23.409 12.1,23.409 12.1,53.34 0,53.34 0,0
GND:
  region: 12.1,0 12.1,15.97 35.965,15.97 35.965,28.043 33.864,28.043 33.864,25.336 33.864,24.519 32.754,23.409 12.1,23.409 12.1,53.34 0,53.34 0,0
SIG:
  region: 12.1,0 12.1,15.97 35.965,15.97 35.965,28.043 33.864,28.043 33.864,25.336 33.864,24.519 32.754,23.409 12.1,23.409 12.1,53.34 0,53.34 0,0
BOTTOM:
  region: 12.1,0 12.1,15.97 35.965,15.97 35.965,28.043 33.864,28.043 33.864,25.336 33.864,24.519 32.754,23.409 12.1,23.409 12.1,53.34 0,53.34 0,0

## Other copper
TOP:
  region net +5V: 15.5,38.2 15.5,39.682 12.9,39.682 12.9,38.2
  region net VIN: 13.6,36.595 13.6,34.095 16.56,34.095 16.56,36.595
  text ".Version" at 15.59,3.99 h1
BOTTOM:
  rectangle net GND: 12.656,0.603 17.461,5.502
  region net GND: 39.629,18.945 42.829,18.945 42.829,13.5 39.629,13.5
  region net GND: 45.929,22.1 50.196,22.1 50.196,13.5 45.929,13.5

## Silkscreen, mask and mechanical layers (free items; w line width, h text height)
Top Overlay:
  drawing of 149 lines, arcs and shapes, not listed
Bottom Overlay:
  drawing of 176 lines, arcs and shapes, not listed
Route Tool Path:
  lines w2: -1,6.306 -1,1 ccw(c1,1) 1,-1 65.04,-1 ccw(c65.04,1) 67.04,1 67.04,2.126 69.287,4.373 ; -1,14.306 -1,31.866 ; -1,39.866 -1,52.34 cw(c1,52.34) 1,54.34 64.516,54.34 ; 69.58,17.463 69.58,5.08 ; 69.58,25.463 69.58,37.846 ; 64.516,54.34 cw(c64.516,53.34) 65.223,54.047 ; 64.516,54.34 cw(c64.516,53.34) 65.223,54.047 ; 65.223,54.047 66.747,52.523 ; 66.747,52.523 cw(c66.04,51.816) 67.04,51.816 ; 66.747,52.523 cw(c66.04,51.816) 67.04,51.816 ; 67.04,51.816 67.04,40.8 69.287,38.553 ; 69.287,4.373 ccw(c68.58,5.08) 69.58,5.08 ; 69.287,4.373 ccw(c68.58,5.08) 69.58,5.08 ; 69.287,38.553 cw(c68.58,37.846) 69.58,37.846 ; 69.287,38.553 cw(c68.58,37.846) 69.58,37.846
Board:
  lines w0.127: 1,0 cw(c1,1) 0,1 0,52.34 cw(c1,52.34) 1,53.34 ; 1,0 65.04,0 ; 1,0 65.04,0 ; 1,53.34 64.516,53.34 ; 1,53.34 64.516,53.34 ; 64.516,53.34 66.04,51.816 ; 64.516,53.34 66.04,51.816 ; 65.04,0 ccw(c65.04,1) 66.04,1 ; 66.04,1 66.04,2.54 ; 66.04,1 66.04,2.54 ; 66.04,2.54 68.58,5.08 ; 66.04,2.54 68.58,5.08 ; 66.04,40.386 68.58,37.846 ; 66.04,40.386 66.04,51.816 ; 66.04,40.386 66.04,51.816 ; 66.04,40.386 68.58,37.846 ; 68.58,5.08 68.58,37.846 ; 68.58,5.08 68.58,37.846
Mechanical 73:
  circle w0.013: c48.26,2.54 r0.305
  circle w0.013: c27.94,2.54 r0.425
  circle w0.013: c30.48,2.54 r0.425
  circle w0.013: c33.02,2.54 r0.425
  circle w0.013: c35.56,2.54 r0.425
  circle w0.013: c38.1,2.54 r0.425
  circle w0.013: c40.64,2.54 r0.425
  circle w0.013: c43.18,2.54 r0.425
  circle w0.013: c45.72,2.54 r0.425
  circle w0.013: c50.8,2.54 r0.425
  circle w0.013: c53.34,2.54 r0.425
  circle w0.013: c55.88,2.54 r0.425
  circle w0.013: c58.42,2.54 r0.425
  circle w0.013: c60.96,2.54 r0.425
  circle w0.013: c63.5,2.54 r0.425
  circle w0.013: c63.5,50.8 r0.425
  circle w0.013: c60.96,50.8 r0.425
  circle w0.013: c58.42,50.8 r0.425
  circle w0.013: c55.88,50.8 r0.425
  circle w0.013: c53.34,50.8 r0.425
  circle w0.013: c50.8,50.8 r0.425
  circle w0.013: c48.26,50.8 r0.425
  circle w0.013: c45.72,50.8 r0.425
  circle w0.013: c41.656,50.8 r0.425
  circle w0.013: c39.116,50.8 r0.425
  circle w0.013: c36.576,50.8 r0.425
  circle w0.013: c34.036,50.8 r0.425
  circle w0.013: c31.496,50.8 r0.425
  circle w0.013: c28.956,50.8 r0.425
  circle w0.013: c26.416,50.8 r0.425
  circle w0.013: c23.876,50.8 r0.425
  circle w0.013: c21.336,50.8 r0.425
  circle w0.013: c18.796,50.8 r0.425
  circle w0.013: c63.627,25.4 r0.475
  circle w0.013: c66.167,25.4 r0.475
  circle w0.013: c66.167,27.94 r0.475
  circle w0.013: c63.627,27.94 r0.475
  circle w0.013: c63.627,30.48 r0.475
  circle w0.013: c66.167,30.48 r0.475
  circle w0.013: c13.97,2.54 r1.6
  circle w0.013: c66.04,7.62 r1.6
  circle w0.013: c66.04,35.56 r1.6
  circle w0.013: c15.24,50.8 r1.6
  circle w0.013: c22.86,2.54 r0.425
  circle w0.013: c20.32,2.54 r0.425
  circle w0.013: c17.78,2.54 r0.425
  lines w0.05: 5.44,8.056 5.69,8.306 ; 5.44,8.556 5.69,8.306 ; 5.94,8.056 5.69,8.306 ; 5.94,8.556 5.69,8.306 ; 8.49,3.106 8.74,3.356 ; 8.49,3.606 8.74,3.356 ; 8.99,3.106 8.74,3.356 ; 8.99,3.606 8.74,3.356 ; 11.64,8.056 11.89,8.306 ; 11.64,8.556 11.89,8.306 ; 12.14,8.056 11.89,8.306 ; 12.14,8.556 11.89,8.306 ; -1.96,3.456 12.44,3.456 12.44,12.856 -1.96,12.856 -1.96,3.456 ; -0.86,33.106 -0.86,42.656 5.94,42.656 5.94,41.706 5.94,33.106 3.19,33.106 -0.86,33.106 ; 5.19,7.406 ccw(c5.69,7.406) 5.69,6.906 ccw(c5.69,7.406) 6.19,7.406 6.19,8.306 6.19,9.206 ccw(c5.69,9.206) 5.69,9.706 ccw(c5.69,9.206) 5.19,9.206 5.19,8.306 5.19,7.406 ; 7.34,3.356 cw(c7.84,3.356) 7.84,3.856 8.74,3.856 9.64,3.856 cw(c9.64,3.356) 10.14,3.356 cw(c9.64,3.356) 9.64,2.856 8.74,2.856 7.84,2.856 cw(c7.84,3.356) 7.34,3.356 ; 11.39,7.406 ccw(c11.89,7.406) 11.89,6.906 ccw(c11.89,7.406) 12.39,7.406 12.39,8.306 12.39,9.206 ccw(c11.89,9.206) 11.89,9.706 ccw(c11.89,9.206) 11.39,9.206 11.39,8.306 11.39,7.406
